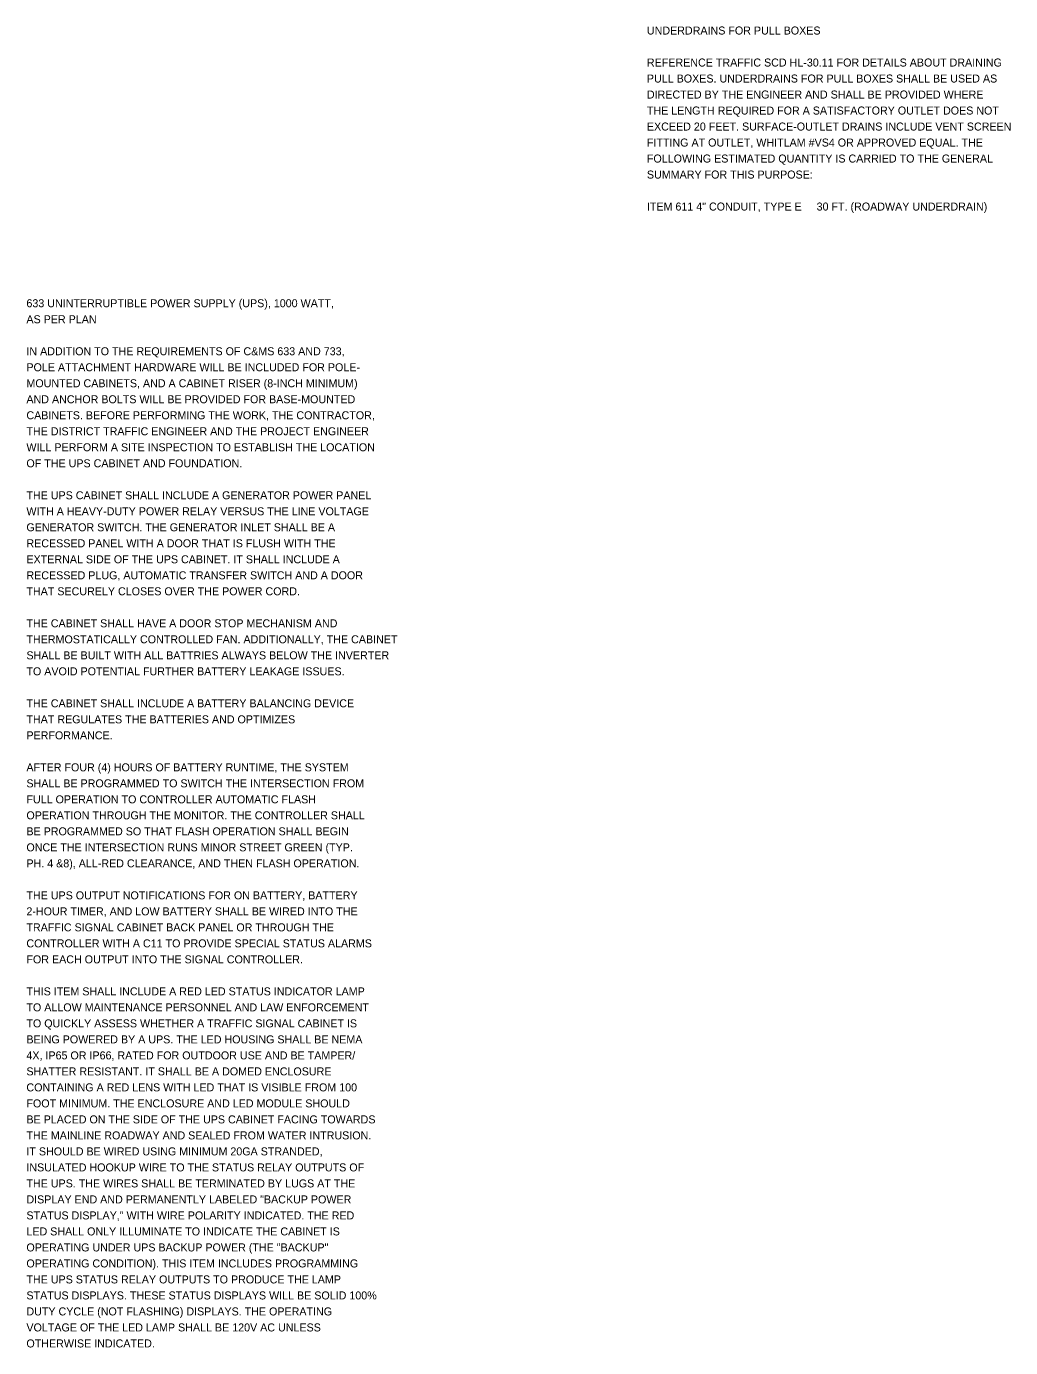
# Model space of a CAD drawing. Extents: x 0 to 54.7, y -11 to 22.
# Drawn here: x 37.49 to 54.71, y -8.94 to 14.17 of the extents above; entities that cross this region are included whole.
import ezdxf

# ---------------------------------------------------------------- set-up
doc = ezdxf.new("R2010")
doc.units = 0
doc.layers.add('SH_Text', color=7, linetype='Continuous')

msp = doc.modelspace()

# ---------------------------------------------------------------- texts
at = {"layer": 'SH_Text'}
for s, p in [('UNDERDRAINS FOR PULL BOXES', (48.344, 14.03)), ('REFERENCE TRAFFIC SCD HL-30.11 FOR DETAILS ABOUT DRAINING', (48.344, 13.47)), ('PULL BOXES. UNDERDRAINS FOR PULL BOXES SHALL BE USED AS', (48.344, 13.19)), ('DIRECTED BY THE ENGINEER AND SHALL BE PROVIDED WHERE', (48.344, 12.91)), ('THE LENGTH REQUIRED FOR A SATISFACTORY OUTLET DOES NOT', (48.344, 12.63)), ('EXCEED 20 FEET. SURFACE-OUTLET DRAINS INCLUDE VENT SCREEN', (48.344, 12.35)), ('FITTING AT OUTLET, WHITLAM #VS4 OR APPROVED EQUAL. THE', (48.344, 12.07)), ('FOLLOWING ESTIMATED QUANTITY IS CARRIED TO THE GENERAL', (48.344, 11.79)), ('SUMMARY FOR THIS PURPOSE:', (48.344, 11.51)), ('ITEM 611 4" CONDUIT, TYPE E     30 FT. (ROADWAY UNDERDRAIN)', (48.344, 10.95)), ('633 UNINTERRUPTIBLE POWER SUPPLY (UPS), 1000 WATT,', (37.49, 9.258)), ('AS PER PLAN', (37.49, 8.978)), ('IN ADDITION TO THE REQUIREMENTS OF C&MS 633 AND 733,', (37.49, 8.418)), ('POLE ATTACHMENT HARDWARE WILL BE INCLUDED FOR POLE-', (37.49, 8.138)), ('MOUNTED CABINETS, AND A CABINET RISER (8-INCH MINIMUM)', (37.49, 7.858)), ('AND ANCHOR BOLTS WILL BE PROVIDED FOR BASE-MOUNTED', (37.49, 7.578)), ('CABINETS. BEFORE PERFORMING THE WORK, THE CONTRACTOR,', (37.49, 7.298)), ('THE DISTRICT TRAFFIC ENGINEER AND THE PROJECT ENGINEER', (37.49, 7.018)), ('WILL PERFORM A SITE INSPECTION TO ESTABLISH THE LOCATION', (37.49, 6.738)), ('OF THE UPS CABINET AND FOUNDATION.', (37.49, 6.458)), ('THE UPS CABINET SHALL INCLUDE A GENERATOR POWER PANEL', (37.49, 5.898)), ('WITH A HEAVY-DUTY POWER RELAY VERSUS THE LINE VOLTAGE', (37.49, 5.618)), ('GENERATOR SWITCH. THE GENERATOR INLET SHALL BE A', (37.49, 5.338)), ('RECESSED PANEL WITH A DOOR THAT IS FLUSH WITH THE', (37.49, 5.058)), ('EXTERNAL SIDE OF THE UPS CABINET. IT SHALL INCLUDE A', (37.49, 4.778)), ('RECESSED PLUG, AUTOMATIC TRANSFER SWITCH AND A DOOR', (37.49, 4.498)), ('THAT SECURELY CLOSES OVER THE POWER CORD.', (37.49, 4.218)), ('THE CABINET SHALL HAVE A DOOR STOP MECHANISM AND', (37.49, 3.658)), ('THERMOSTATICALLY CONTROLLED FAN. ADDITIONALLY, THE CABINET', (37.49, 3.378)), ('SHALL BE BUILT WITH ALL BATTRIES ALWAYS BELOW THE INVERTER', (37.49, 3.098)), ('TO AVOID POTENTIAL FURTHER BATTERY LEAKAGE ISSUES.', (37.49, 2.818)), ('THE CABINET SHALL INCLUDE A BATTERY BALANCING DEVICE', (37.49, 2.258)), ('THAT REGULATES THE BATTERIES AND OPTIMIZES', (37.49, 1.978)), ('PERFORMANCE.', (37.49, 1.698)), ('AFTER FOUR (4) HOURS OF BATTERY RUNTIME, THE SYSTEM', (37.49, 1.138)), ('SHALL BE PROGRAMMED TO SWITCH THE INTERSECTION FROM', (37.49, 0.858)), ('FULL OPERATION TO CONTROLLER AUTOMATIC FLASH', (37.49, 0.578)), ('OPERATION THROUGH THE MONITOR. THE CONTROLLER SHALL', (37.49, 0.298)), ('BE PROGRAMMED SO THAT FLASH OPERATION SHALL BEGIN', (37.49, 0.018)), ('ONCE THE INTERSECTION RUNS MINOR STREET GREEN (TYP.', (37.49, -0.262)), ('PH. 4 &8), ALL-RED CLEARANCE, AND THEN FLASH OPERATION.', (37.49, -0.542)), ('THE UPS OUTPUT NOTIFICATIONS FOR ON BATTERY, BATTERY', (37.49, -1.102)), ('2-HOUR TIMER, AND LOW BATTERY SHALL BE WIRED INTO THE', (37.49, -1.382)), ('TRAFFIC SIGNAL CABINET BACK PANEL OR THROUGH THE', (37.49, -1.662)), ('CONTROLLER WITH A C11 TO PROVIDE SPECIAL STATUS ALARMS', (37.49, -1.942)), ('FOR EACH OUTPUT INTO THE SIGNAL CONTROLLER.', (37.49, -2.222)), ('THIS ITEM SHALL INCLUDE A RED LED STATUS INDICATOR LAMP', (37.49, -2.782)), ('TO ALLOW MAINTENANCE PERSONNEL AND LAW ENFORCEMENT', (37.49, -3.062)), ('TO QUICKLY ASSESS WHETHER A TRAFFIC SIGNAL CABINET IS', (37.49, -3.342)), ('BEING POWERED BY A UPS. THE LED HOUSING SHALL BE NEMA', (37.49, -3.622)), ('4X, IP65 OR IP66, RATED FOR OUTDOOR USE AND BE TAMPER/', (37.49, -3.902)), ('SHATTER RESISTANT. IT SHALL BE A DOMED ENCLOSURE', (37.49, -4.182)), ('CONTAINING A RED LENS WITH LED THAT IS VISIBLE FROM 100', (37.49, -4.462)), ('FOOT MINIMUM. THE ENCLOSURE AND LED MODULE SHOULD', (37.49, -4.742)), ('BE PLACED ON THE SIDE OF THE UPS CABINET FACING TOWARDS', (37.49, -5.022)), ('THE MAINLINE ROADWAY AND SEALED FROM WATER INTRUSION.', (37.49, -5.302)), ('IT SHOULD BE WIRED USING MINIMUM 20GA STRANDED,', (37.49, -5.582)), ('INSULATED HOOKUP WIRE TO THE STATUS RELAY OUTPUTS OF', (37.49, -5.862)), ('THE UPS. THE WIRES SHALL BE TERMINATED BY LUGS AT THE', (37.49, -6.142)), ('DISPLAY END AND PERMANENTLY LABELED "BACKUP POWER', (37.49, -6.422)), ('STATUS DISPLAY," WITH WIRE POLARITY INDICATED. THE RED', (37.49, -6.702)), ('LED SHALL ONLY ILLUMINATE TO INDICATE THE CABINET IS', (37.49, -6.982)), ('OPERATING UNDER UPS BACKUP POWER (THE "BACKUP"', (37.49, -7.262)), ('OPERATING CONDITION). THIS ITEM INCLUDES PROGRAMMING', (37.49, -7.542)), ('THE UPS STATUS RELAY OUTPUTS TO PRODUCE THE LAMP', (37.49, -7.822)), ('STATUS DISPLAYS. THESE STATUS DISPLAYS WILL BE SOLID 100%', (37.49, -8.102)), ('DUTY CYCLE (NOT FLASHING) DISPLAYS. THE OPERATING', (37.49, -8.382)), ('VOLTAGE OF THE LED LAMP SHALL BE 120V AC UNLESS', (37.49, -8.662)), ('OTHERWISE INDICATED.', (37.49, -8.942))]:
    msp.add_text(s, height=0.14, dxfattribs=at).set_placement(p)

doc.saveas('drawing.dxf')
